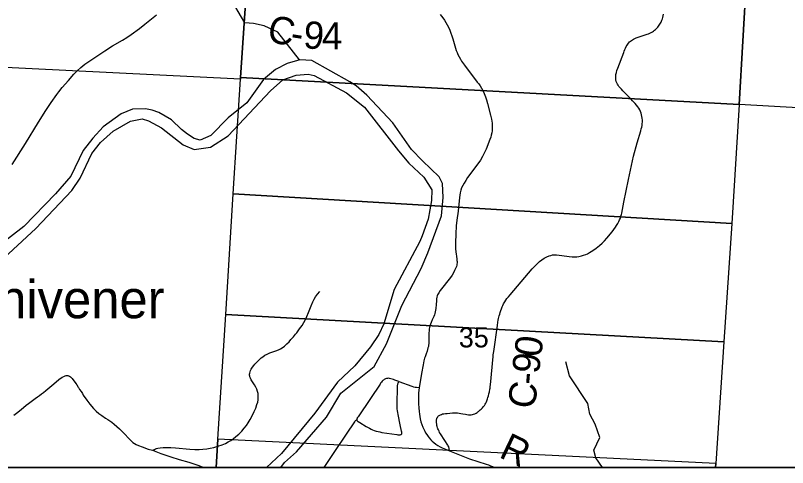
# Model space of a CAD drawing. Extents: x 0 to 34, y 0 to 22.
# Drawn here: x 26.889 to 28.495, y 14.1 to 15.04 of the extents above; entities that cross this region are included whole.
import ezdxf

# ---------------------------------------------------------------- set-up
doc = ezdxf.new("R2010")
doc.units = 0
for name, color, linetype in [('Default', 7, 'Continuous'), ('GM_X_County_Road', 7, 'Continuous'), ('GM_X_County_Road_Text', 7, 'Continuous'), ('GM_X_Major_River', 7, 'Continuous'), ('GM_X_Minor_River', 7, 'Continuous'), ('GM_X_Section', 7, 'Continuous'), ('GM_X_Section_Text', 7, 'Continuous'), ('GM_X_State_Route', 7, 'Continuous'), ('GM_X_Township_Road', 7, 'Continuous'), ('GM_X_Unincorporated_Text', 7, 'Continuous'), ('SH_Data', 7, 'Continuous'), ('SH_Text', 7, 'Continuous')]:
    doc.layers.add(name, color=color, linetype=linetype)

msp = doc.modelspace()

# ---------------------------------------------------------------- linework, layer by layer
at = {"layer": 'Default'}
for points in [[(26.2424, 14.1), (27.3064, 14.1), (27.3102, 14.1589), (27.3266, 14.4183), (27.342, 14.6691), (27.3572, 14.9074), (26.2944, 14.9601)], [(28.345, 14.1), (29.3762, 14.1), (29.4168, 14.6926), (29.4251, 14.7203), (29.4211, 14.7771), (29.4209, 14.7772), (29.388, 14.8008), (28.6267, 14.8415), (28.3943, 14.8549), (28.3788, 14.6076), (28.3627, 14.3611), (28.3456, 14.1084)], [(27.3064, 14.1), (28.345, 14.1), (28.3456, 14.1084), (27.3102, 14.1589)]]:
    msp.add_lwpolyline(points, close=True, dxfattribs=at)
msp.add_lwpolyline([(26.2331, 14.1), (29.5051, 14.1)], dxfattribs=at)
at = {"layer": 'GM_X_County_Road'}
for points in [[(27.7725, 15.042), (27.7754, 15.0386), (27.7783, 15.0349), (27.7814, 15.0302), (27.7845, 15.0252), (27.7872, 15.0204), (27.7902, 15.0146), (27.7926, 15.0091), (27.7949, 15.0035), (27.7969, 14.9976), (27.7988, 14.9915), (27.8044, 14.9719), (27.8059, 14.9672), (27.8076, 14.9628), (27.8093, 14.9587), (27.8117, 14.9539), (27.8144, 14.9492), (27.817, 14.9453), (27.8232, 14.9367), (27.8496, 14.9016), (27.8527, 14.8976), (27.8554, 14.8937), (27.8585, 14.8889), (27.8611, 14.8843), (27.8641, 14.8777), (27.8667, 14.8709), (27.8689, 14.8644), (27.8712, 14.8567), (27.8773, 14.8328), (27.879, 14.8243), (27.8798, 14.8201), (27.8804, 14.8159), (27.8809, 14.8102), (27.8809, 14.8052), (27.8804, 14.8002), (27.8797, 14.7958), (27.8787, 14.7913), (27.8775, 14.7872), (27.8758, 14.7822), (27.8678, 14.7621), (27.864, 14.7538), (27.8607, 14.747), (27.856, 14.7389), (27.8509, 14.7312), (27.8296, 14.703), (27.8256, 14.6971), (27.8221, 14.6915), (27.8194, 14.6867), (27.817, 14.6813), (27.8153, 14.6765), (27.8141, 14.671), (27.8133, 14.6665), (27.8126, 14.6617), (27.8098, 14.633), (27.807, 14.6144), (27.8064, 14.6082), (27.8058, 14.6033), (27.8054, 14.5973), (27.8052, 14.5912), (27.8042, 14.5619), (27.8043, 14.5545), (27.8048, 14.5483), (27.8054, 14.5438), (27.8062, 14.5392), (27.8071, 14.5335), (27.8074, 14.5307), (27.8075, 14.5283), (27.8075, 14.5258), (27.8073, 14.5231), (27.8069, 14.5207), (27.8063, 14.5181), (27.8046, 14.514), (27.8025, 14.5094), (27.8, 14.5049), (27.7972, 14.5003), (27.7936, 14.4952), (27.7724, 14.4678), (27.7694, 14.4632), (27.7682, 14.4609), (27.7672, 14.4588), (27.7663, 14.4567), (27.7656, 14.4543), (27.7649, 14.4507), (27.7645, 14.4468), (27.7638, 14.439), (27.7631, 14.4308), (27.7626, 14.4271), (27.7621, 14.4238), (27.7614, 14.4206), (27.7603, 14.4174), (27.759, 14.4139), (27.7559, 14.4069), (27.7538, 14.4017), (27.7523, 14.3981), (27.7512, 14.3947), (27.7502, 14.3913), (27.7496, 14.3881), (27.7492, 14.3841), (27.749, 14.38), (27.7489, 14.371), (27.7488, 14.362), (27.7486, 14.3578), (27.7482, 14.3546), (27.7478, 14.3518), (27.7471, 14.3487), (27.7463, 14.3454), (27.7451, 14.3421), (27.7431, 14.3363), (27.741, 14.3304), (27.7401, 14.3277), (27.7393, 14.3248), (27.7386, 14.3216), (27.7378, 14.318), (27.737, 14.3139), (27.7337, 14.2955), (27.7307, 14.2779), (27.729, 14.2665), (27.728, 14.2599), (27.7275, 14.2556), (27.7272, 14.2513), (27.727, 14.2473), (27.727, 14.2431), (27.7271, 14.2384), (27.7273, 14.2326), (27.7279, 14.2241), (27.7286, 14.2164), (27.7293, 14.2108), (27.73, 14.2062), (27.731, 14.201), (27.7323, 14.1952), (27.734, 14.1895), (27.7362, 14.1839), (27.7383, 14.1795), (27.7402, 14.1759), (27.742, 14.1725), (27.7446, 14.1684), (27.7472, 14.1647), (27.7498, 14.1616), (27.7531, 14.1578), (27.7561, 14.155), (27.7595, 14.1519), (27.7637, 14.1485), (27.7677, 14.1458), (27.7721, 14.1434), (27.7765, 14.1413), (27.7833, 14.1382), (27.792, 14.1345), (27.8089, 14.1279), (27.8336, 14.1182), (27.8681, 14.1068), (27.8727, 14.1054), (27.8769, 14.1039), (27.8815, 14.1021), (27.8863, 14.1)], [(27.792, 14.1345), (27.7914, 14.1388), (27.7911, 14.1404), (27.7907, 14.1417), (27.7902, 14.1433), (27.7894, 14.1449), (27.7885, 14.1463), (27.782, 14.1559), (27.7731, 14.1701), (27.7713, 14.1731), (27.77, 14.1757), (27.7688, 14.1781), (27.7678, 14.1806), (27.767, 14.1829), (27.7663, 14.1853), (27.7657, 14.1877), (27.7652, 14.1903), (27.7648, 14.1934), (27.7647, 14.1963), (27.7647, 14.1982), (27.765, 14.2), (27.7653, 14.2013), (27.7658, 14.2028), (27.7667, 14.2044), (27.7677, 14.2058), (27.769, 14.2073), (27.7705, 14.2085), (27.7716, 14.2092), (27.7729, 14.2099), (27.7749, 14.2106), (27.7772, 14.2114), (27.7797, 14.2119), (27.7832, 14.2124), (27.7867, 14.2127), (27.7978, 14.2136), (27.8018, 14.2138), (27.8049, 14.2138), (27.8082, 14.2136), (27.8117, 14.2132), (27.8156, 14.2125), (27.8197, 14.2117), (27.8248, 14.2107), (27.828, 14.2101), (27.8311, 14.2096), (27.834, 14.2094), (27.8366, 14.2096), (27.8394, 14.21), (27.842, 14.2108), (27.8442, 14.2117), (27.847, 14.213), (27.8492, 14.2144), (27.8509, 14.2156), (27.8524, 14.2167), (27.8538, 14.2179), (27.8558, 14.2197), (27.8579, 14.2217), (27.8606, 14.2245), (27.8628, 14.227), (27.8646, 14.2292), (27.8663, 14.2318), (27.8676, 14.2342), (27.8687, 14.2363), (27.8696, 14.2387), (27.8704, 14.2406), (27.8711, 14.2429), (27.8719, 14.2457), (27.8729, 14.2491), (27.8739, 14.2535), (27.8748, 14.2576), (27.8757, 14.2627), (27.8761, 14.2654), (27.8765, 14.2685), (27.8768, 14.2719), (27.8826, 14.3309), (27.8829, 14.3345), (27.8833, 14.3377), (27.8838, 14.3415), (27.8916, 14.3957), (27.8926, 14.4026), (27.8933, 14.4066), (27.894, 14.41), (27.8946, 14.4127), (27.8954, 14.4157), (27.8963, 14.4187), (27.8975, 14.4226), (27.8988, 14.4265), (27.9001, 14.4303), (27.9015, 14.4339), (27.9027, 14.4371), (27.9045, 14.4407), (27.9068, 14.4446), (27.9091, 14.4482), (27.9113, 14.4516), (27.9143, 14.4552), (27.9177, 14.4594), (27.9641, 14.513), (27.9692, 14.5188), (27.9742, 14.5238), (27.9792, 14.5283), (27.9841, 14.5321), (27.9887, 14.5351), (27.9941, 14.5379), (27.9992, 14.5401), (28.0026, 14.5412), (28.0062, 14.542), (28.0104, 14.5424), (28.0146, 14.5424), (28.0201, 14.5418), (28.0357, 14.5392), (28.0411, 14.5386), (28.0467, 14.5382), (28.0515, 14.5381), (28.0564, 14.5383), (28.0608, 14.5389), (28.0662, 14.5399), (28.0709, 14.5414), (28.0755, 14.5431), (28.0789, 14.5446), (28.0832, 14.5471), (28.0901, 14.5513), (28.0967, 14.5559), (28.104, 14.5616), (28.1097, 14.5665), (28.1144, 14.5712), (28.1194, 14.5768), (28.1302, 14.5901), (28.1371, 14.5997), (28.1395, 14.6035), (28.1419, 14.6076), (28.144, 14.6115), (28.1458, 14.6151), (28.1473, 14.6187), (28.1485, 14.6224), (28.1494, 14.626), (28.1502, 14.6288), (28.1548, 14.6516), (28.1643, 14.699), (28.1748, 14.7474), (28.182, 14.7755), (28.1896, 14.8), (28.1908, 14.8041), (28.1917, 14.8076), (28.1923, 14.8113), (28.1927, 14.815), (28.193, 14.8185), (28.1931, 14.8223), (28.1928, 14.8263), (28.1922, 14.8302), (28.1914, 14.8337), (28.1905, 14.8366), (28.1891, 14.8401), (28.1876, 14.8436), (28.1857, 14.8469), (28.1836, 14.8499), (28.1807, 14.8535), (28.1779, 14.8569), (28.1752, 14.8598), (28.1727, 14.8625), (28.169, 14.8664), (28.1523, 14.8832), (28.1493, 14.8865), (28.1466, 14.8895), (28.1443, 14.8923), (28.1426, 14.8948), (28.1412, 14.8972), (28.1397, 14.9001), (28.1387, 14.9028), (28.138, 14.9061), (28.1376, 14.91), (28.1376, 14.9132), (28.138, 14.917), (28.1389, 14.9213), (28.1401, 14.9255), (28.1419, 14.9304), (28.1542, 14.9629), (28.1555, 14.9661), (28.1567, 14.9691), (28.1581, 14.9723), (28.1596, 14.9753), (28.1611, 14.9782), (28.1625, 14.9803), (28.1641, 14.9826), (28.1662, 14.9849), (28.1681, 14.9866), (28.1702, 14.9882), (28.1724, 14.9895), (28.1747, 14.9907), (28.1773, 14.9919), (28.1804, 14.9932), (28.2029, 15.0008), (28.2058, 15.002), (28.2084, 15.0031), (28.2111, 15.0044), (28.2139, 15.006), (28.2164, 15.0076), (28.2186, 15.0092), (28.2205, 15.0108), (28.2224, 15.0126), (28.2239, 15.0141), (28.2252, 15.0157), (28.2267, 15.0175), (28.2281, 15.0196), (28.2295, 15.0217), (28.2306, 15.0238), (28.2318, 15.0262), (28.2328, 15.0281), (28.2337, 15.0302), (28.2346, 15.0327), (28.2356, 15.0358), (28.2365, 15.039), (28.2373, 15.0427)], [(26.8856, 14.209), (26.891, 14.2131), (26.9006, 14.2208), (26.9115, 14.2298), (26.9158, 14.2333), (26.9241, 14.2396), (26.9302, 14.2439), (26.9347, 14.2471), (26.9388, 14.2499), (26.9433, 14.253), (26.9472, 14.2561), (26.9524, 14.2604), (26.9646, 14.2709), (26.9736, 14.2784), (26.9795, 14.283), (26.9861, 14.2876), (26.9893, 14.2895), (26.9922, 14.2908), (26.9946, 14.2913), (26.9964, 14.2914), (26.9982, 14.2912), (26.9994, 14.2909), (27.0011, 14.2902), (27.0036, 14.2884), (27.0066, 14.2853), (27.0147, 14.2745), (27.0165, 14.2719), (27.0196, 14.267)], [(27.0196, 14.267), (27.0201, 14.2662), (27.0224, 14.2625), (27.0253, 14.2578), (27.0281, 14.2537), (27.0301, 14.2506), (27.0376, 14.2399), (27.0436, 14.232), (27.0513, 14.2231), (27.057, 14.2173), (27.0626, 14.2124), (27.0685, 14.2079), (27.0762, 14.2026), (27.0809, 14.1996), (27.0892, 14.1941), (27.0946, 14.19), (27.0999, 14.1856), (27.1053, 14.1806), (27.1145, 14.1715), (27.1261, 14.1589), (27.1301, 14.155), (27.1334, 14.1523), (27.1364, 14.1502), (27.1402, 14.1481), (27.1446, 14.146), (27.1527, 14.1429), (27.1649, 14.1384), (27.174, 14.1358), (27.1912, 14.1294), (27.1999, 14.1262), (27.2123, 14.1221), (27.2296, 14.1168), (27.2498, 14.111), (27.2682, 14.105), (27.274, 14.1029), (27.279, 14.1005), (27.2799, 14.1)]]:
    msp.add_lwpolyline(points, dxfattribs=at)
at = {"layer": 'GM_X_Major_River'}
for points in [[(27.4407, 14.1), (27.4486, 14.1105), (27.4735, 14.1326), (27.5359, 14.2047), (27.5658, 14.2546), (27.6351, 14.3104), (27.6606, 14.3572), (27.6651, 14.3678), (27.6927, 14.437), (27.7331, 14.5139), (27.7469, 14.5462), (27.7749, 14.6234), (27.7784, 14.6614), (27.7772, 14.6909), (27.7703, 14.7046), (27.7357, 14.7377), (27.7125, 14.7615), (27.674, 14.8167), (27.62, 14.874), (27.5975, 14.894), (27.5846, 14.9023), (27.5057, 14.9462), (27.4804, 14.9476), (27.4543, 14.9398), (27.4298, 14.9279), (27.4046, 14.9065), (27.3701, 14.8585), (27.3316, 14.8272), (27.2955, 14.7905), (27.2733, 14.7809), (27.2604, 14.7839), (27.2471, 14.7929), (27.2346, 14.8031), (27.2133, 14.8231), (27.1871, 14.8385), (27.1731, 14.8433), (27.1595, 14.8459), (27.1322, 14.8454), (27.1085, 14.8357), (27.0712, 14.8082), (27.0501, 14.7849), (27.0298, 14.7594), (27.004, 14.7061), (26.9725, 14.6688), (26.9063, 14.6012), (26.8565, 14.563)], [(26.8266, 14.5006), (26.9313, 14.5968), (27.0065, 14.6758), (27.0237, 14.7017), (27.0476, 14.7527), (27.0657, 14.7759), (27.0924, 14.7996), (27.1282, 14.8203), (27.1528, 14.8254), (27.166, 14.8209), (27.1926, 14.8063), (27.2378, 14.7709), (27.2605, 14.7615), (27.2945, 14.7659), (27.3311, 14.79), (27.4195, 14.8831), (27.4451, 14.906), (27.473, 14.916), (27.4976, 14.9181), (27.5104, 14.9155), (27.5779, 14.8791), (27.6148, 14.8493), (27.686, 14.7587), (27.7073, 14.733), (27.7381, 14.704), (27.7549, 14.6772), (27.7547, 14.6552), (27.7473, 14.6164), (27.735, 14.5818), (27.7302, 14.5697), (27.677, 14.4703), (27.6551, 14.3989), (27.645, 14.3764), (27.6277, 14.3509), (27.595, 14.3116), (27.5589, 14.2777), (27.512, 14.2129), (27.4421, 14.129), (27.4112, 14.1)]]:
    msp.add_lwpolyline(points, dxfattribs=at)
at = {"layer": 'GM_X_Minor_River'}
for points in [[(27.4801, 14.9479), (27.4347, 15.0056), (27.406, 15.0186), (27.3843, 15.0231), (27.3658, 15.0245), (27.3335, 15.081), (27.3251, 15.104), (27.3189, 15.1354), (27.3177, 15.1597), (27.3275, 15.1852), (27.338, 15.2316), (27.3571, 15.2625), (27.3674, 15.2906), (27.3616, 15.3113), (27.3495, 15.3246), (27.3115, 15.3728)], [(28.1104, 14.1), (28.0959, 14.1202), (28.0918, 14.1362), (28.1047, 14.1628), (28.095, 14.1901), (28.0839, 14.2109), (28.0796, 14.2335), (28.0413, 14.2905), (28.0339, 14.3196)]]:
    msp.add_lwpolyline(points, dxfattribs=at)
at = {"layer": 'GM_X_Section'}
for points in [[(26.3734, 15.9843), (27.4216, 15.9328), (27.4099, 15.6936), (27.392, 15.4391), (27.3753, 15.1787), (27.3574, 14.9107), (27.3572, 14.9074), (26.2944, 14.9601)], [(28.4533, 15.8787), (28.6965, 15.8662), (28.6747, 15.5464), (28.6572, 15.29), (28.6412, 15.0549), (28.6267, 14.8415), (28.3943, 14.8549), (28.4095, 15.1186), (28.4242, 15.3738), (28.439, 15.6312)], [(28.4095, 15.1186), (28.3943, 14.8549), (27.3574, 14.9107), (27.3753, 15.1787)], [(27.3574, 14.9107), (28.3943, 14.8549), (28.3788, 14.6076), (27.342, 14.6691), (27.3572, 14.9074)], [(28.3788, 14.6076), (28.3627, 14.3611), (27.3266, 14.4183), (27.342, 14.6691)], [(27.3266, 14.4183), (28.3627, 14.3611), (28.3456, 14.1084), (27.3102, 14.1589)]]:
    msp.add_lwpolyline(points, close=True, dxfattribs=at)
at = {"layer": 'GM_X_State_Route'}
msp.add_lwpolyline([(26.8823, 14.7303), (26.9097, 14.7738), (26.9371, 14.818), (26.9523, 14.8425), (26.9634, 14.859), (26.9753, 14.8757), (26.9794, 14.8814), (26.9862, 14.8899), (26.9992, 14.905), (27.0106, 14.9179), (27.0175, 14.9251), (27.0246, 14.9319), (27.0333, 14.9386), (27.0456, 14.9471), (27.0747, 14.9663), (27.091, 14.9765), (27.1118, 14.9888), (27.1208, 14.9945), (27.1294, 15.0006), (27.1468, 15.0128), (27.1584, 15.0216), (27.1824, 15.0415)], dxfattribs=at)
at = {"layer": 'GM_X_Township_Road'}
for points in [[(27.174, 14.1358), (27.1785, 14.1378), (27.1801, 14.1388), (27.1824, 14.1397), (27.1854, 14.1405), (27.1897, 14.1411), (27.1959, 14.1415), (27.2027, 14.1417), (27.212, 14.1415), (27.222, 14.141), (27.2516, 14.1383), (27.2622, 14.1376), (27.2709, 14.1375), (27.2789, 14.138), (27.2869, 14.1389), (27.2943, 14.1401), (27.3015, 14.1419), (27.3099, 14.1443), (27.3187, 14.1473), (27.3256, 14.1501), (27.3317, 14.1532), (27.337, 14.1564), (27.3421, 14.16), (27.3474, 14.1643), (27.3534, 14.1696), (27.3596, 14.1758), (27.365, 14.1818), (27.3696, 14.1876), (27.3732, 14.1927), (27.3774, 14.1996), (27.3816, 14.2072), (27.3858, 14.2162), (27.3889, 14.2237), (27.3913, 14.2308), (27.3928, 14.2361), (27.3937, 14.241), (27.394, 14.246), (27.394, 14.2503), (27.3935, 14.254), (27.3926, 14.2583), (27.391, 14.2629), (27.3888, 14.2674), (27.3863, 14.2717), (27.3819, 14.2784), (27.3793, 14.2827), (27.3776, 14.286), (27.3768, 14.2884), (27.3764, 14.2901), (27.3761, 14.2918), (27.376, 14.2931), (27.376, 14.2945), (27.3762, 14.2963), (27.3769, 14.2993), (27.3778, 14.3015), (27.3785, 14.3034), (27.3792, 14.3044), (27.3819, 14.3086), (27.3846, 14.3119), (27.387, 14.3147), (27.3896, 14.3174), (27.3951, 14.3232), (27.3999, 14.3278), (27.4032, 14.3305), (27.4079, 14.3335), (27.4122, 14.3358), (27.4178, 14.3383), (27.4242, 14.3405), (27.4307, 14.3429), (27.4364, 14.3451), (27.4404, 14.347), (27.4457, 14.3501), (27.4486, 14.3524), (27.4496, 14.3531), (27.4537, 14.3569), (27.458, 14.3614), (27.4621, 14.366), (27.467, 14.3716), (27.4717, 14.3774), (27.4741, 14.3802), (27.4801, 14.3881), (27.4854, 14.3957), (27.489, 14.4015), (27.4922, 14.4076), (27.4949, 14.4138), (27.4984, 14.4224), (27.5038, 14.4363), (27.5075, 14.4448), (27.5101, 14.4498), (27.5133, 14.4551), (27.5172, 14.4606), (27.5219, 14.4661)], [(27.6861, 14.2787), (27.6782, 14.2818), (27.6751, 14.283), (27.6725, 14.284), (27.6696, 14.2848), (27.667, 14.2853), (27.6647, 14.2856), (27.6628, 14.2855), (27.6609, 14.2852), (27.659, 14.2846), (27.6573, 14.2838), (27.6558, 14.283), (27.6543, 14.2819), (27.653, 14.2807), (27.6517, 14.2793), (27.6504, 14.2778), (27.6486, 14.2753), (27.6474, 14.2735), (27.6277, 14.2434), (27.6015, 14.2056), (27.601, 14.2048), (27.6005, 14.2041), (27.6, 14.2031), (27.5995, 14.2021), (27.5993, 14.2014), (27.5991, 14.2007), (27.599, 14.1997)], [(27.685, 14.2104), (27.6843, 14.2143), (27.6837, 14.218), (27.6832, 14.2222), (27.683, 14.2255), (27.6828, 14.2286), (27.6828, 14.2326), (27.6837, 14.2669), (27.6837, 14.2686), (27.6838, 14.2702), (27.6839, 14.2715), (27.6841, 14.2728), (27.6844, 14.2739), (27.6847, 14.2752), (27.6861, 14.2787), (27.7132, 14.2689), (27.717, 14.2678), (27.7202, 14.2673), (27.7232, 14.267), (27.729, 14.2665)], [(27.531, 14.1), (27.5535, 14.1331), (27.5775, 14.1691), (27.5948, 14.1953), (27.5956, 14.1967), (27.5965, 14.1977), (27.5975, 14.1986), (27.599, 14.1997)], [(27.599, 14.1997), (27.5991, 14.1984), (27.5996, 14.1974), (27.6005, 14.1966), (27.6016, 14.1958), (27.6051, 14.1936), (27.6187, 14.1853), (27.6216, 14.1837), (27.6252, 14.1818), (27.6288, 14.1799), (27.632, 14.1785), (27.6354, 14.1771), (27.639, 14.1758), (27.6431, 14.1747), (27.6468, 14.174), (27.6514, 14.1732), (27.6824, 14.1686), (27.6846, 14.1683), (27.6869, 14.1681), (27.688, 14.1681), (27.6892, 14.1682), (27.6905, 14.1685), (27.6912, 14.1689), (27.6919, 14.1694), (27.6925, 14.1702), (27.6928, 14.1712), (27.6928, 14.1722)], [(27.6928, 14.1722), (27.6926, 14.1733), (27.6923, 14.1754), (27.689, 14.1887), (27.685, 14.2104)]]:
    msp.add_lwpolyline(points, dxfattribs=at)
at = {"layer": 'SH_Data'}
msp.add_lwpolyline([(23.5167, 20.9), (30.3167, 20.9), (30.3167, 14.1), (23.5167, 14.1)], close=True, dxfattribs=at)
at = {"layer": 'SH_Text'}
msp.add_lwpolyline([(23.5167, 14.1), (29.5051, 14.1)], dxfattribs=at)

# ---------------------------------------------------------------- texts
at = {"layer": 'GM_X_County_Road_Text'}
for s, rotation, p in [('C', 348.1983, (27.4101, 14.9866)), ('9', 355.2721, (27.4864, 14.9723)), ('4', 0.07, (27.5265, 14.9692)), ('-', 351.097, (27.4588, 14.9765)), ('0', 81.9542, (27.982, 14.3279)), ('9', 83.35, (27.978, 14.2935)), ('-', 85.3252, (27.9761, 14.2708)), ('C', 80.4007, (27.9677, 14.2195)), ('R', 334.3985, (27.8926, 14.1226))]:
    msp.add_text(s, height=0.0568, rotation=rotation, dxfattribs=at).set_placement(p)
at = {"layer": 'GM_X_Section_Text'}
msp.add_text('35', height=0.04186, rotation=0, dxfattribs=at).set_placement((27.8112, 14.3498))
at = {"layer": 'GM_X_Unincorporated_Text'}
msp.add_text('Thivener', height=0.07898, rotation=0, dxfattribs=at).set_placement((26.7883, 14.4105))

doc.saveas('drawing.dxf')
